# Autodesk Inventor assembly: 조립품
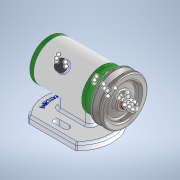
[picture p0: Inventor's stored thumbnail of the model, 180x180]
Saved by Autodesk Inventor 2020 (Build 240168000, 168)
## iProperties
Created: 2022-02
Part Number: 조립품
Document SubType Name: Assembly
Designer: 602-08
Author: 602-08
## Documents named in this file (14)
- C:\Users\602-08\Desktop\720206V1023\답안조립품.iam
- C:\Users\602-08\Desktop\720206V1023\본체.ipt
- C:\Users\602-08\Desktop\720206V1023\뒤커버.ipt
- C:\Users\602-08\Desktop\720206V1023\앞커버.ipt
- C:\Users\602-08\Desktop\720206V1023\축.ipt
- C:\Users\602-08\Desktop\720206V1023\베어링 6002.ipt
- C:\Users\602-08\Desktop\720206V1023\키 3 x 3 x 12.ipt
- C:\Users\602-08\Desktop\720206V1023\오일 실 15 x 25 x 7.ipt
- C:\Users\602-08\Desktop\720206V1023\V벨트풀리.ipt
- C:\Users\602-08\Desktop\720206V1023\너트 M8.ipt
- C:\Users\602-08\Desktop\720206V1023\평와셔 8 x 17.ipt
- C:\Users\602-08\Desktop\720206V1023\스프링와셔 8.ipt
- C:\Users\602-08\Desktop\720206V1023\볼트 M4 x 10.ipt
- C:\Users\602-08\Desktop\720206V1023\고무 캡.ipt
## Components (2 placed, 2 different names)
1. V벨트풀리:1
2. 고무 캡:1
